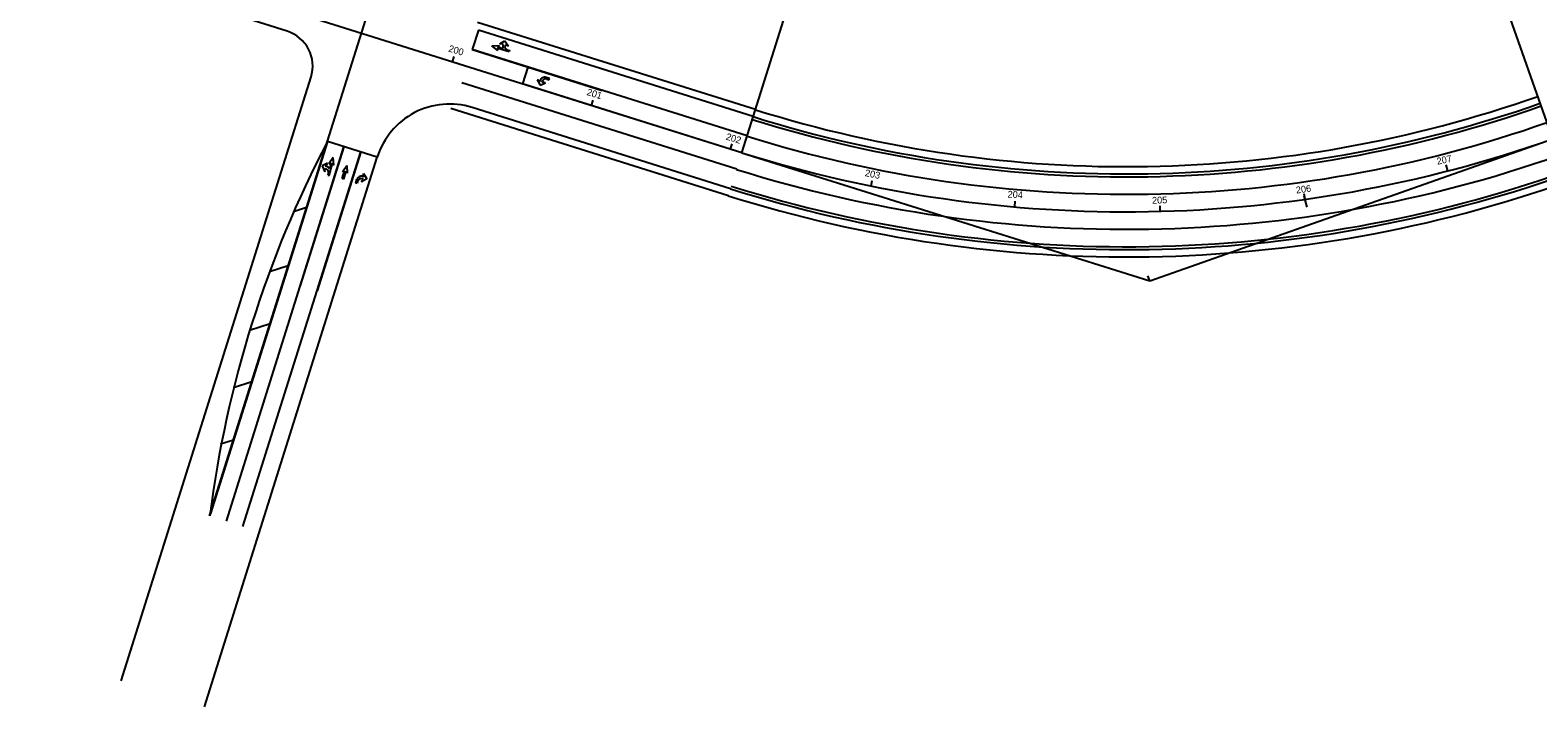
# Model space of a CAD drawing. Extents: x 10803 to 14007, y 6159 to 7440.
# Drawn here: x 10803 to 11838, y 6159 to 6624 of the extents above; entities that cross this region are included whole.
import ezdxf

# ---------------------------------------------------------------- set-up
doc = ezdxf.new("R2010")
doc.units = 0
for name, color, linetype in [('Default', 7, 'Continuous'), ('GE_X_Alignment', 7, 'Continuous'), ('PM_P_Transverse_Line', 7, 'Continuous'), ('PM_X_Cells', 7, 'Continuous'), ('PM_X_Channelizing_Line', 7, 'Continuous'), ('PM_X_CL_Double_Solid', 7, 'Continuous'), ('PM_X_Lane_Line', 7, 'Continuous'), ('PM_X_Stop_Line', 7, 'Continuous'), ('PV_X_Curb', 7, 'Continuous'), ('PV_X_Walk', 7, 'Continuous'), ('SC_Scratch1', 7, 'Continuous')]:
    doc.layers.add(name, color=color, linetype=linetype)

msp = doc.modelspace()

# ---------------------------------------------------------------- linework, layer by layer
at = {"layer": 'Default'}
for p, q in [((11092.8, 6602.1), (11094, 6605.7)), ((11188.2, 6572.1), (11189.4, 6575.7)), ((11283.7, 6542.1), (11284.8, 6545.7)), ((11776.5, 6527.1), (11775.4, 6531.2)), ((11380.3, 6516.7), (11381, 6520.4)), ((11479.1, 6502.4), (11479.4, 6506.2)), ((11678.5, 6507.6), (11677.9, 6511.4)), ((11679.9, 6502.1), (11677.9, 6509.8)), ((11578.9, 6499.4), (11578.8, 6503.1)), ((11571.7, 6451.6), (11570.5, 6454.9))]:
    msp.add_line(p, q, dxfattribs=at)
at = {"layer": 'GE_X_Alignment'}
for p, q in [((10925.9, 6290.1), (11285.2, 7433.1)), ((11291.6, 6539.6), (10806.8, 6692))]:
    msp.add_line(p, q, dxfattribs=at)
msp.add_arc((11555.8, 7380.5), 881.5, 252.5526, 289.4022, dxfattribs=at)
at = {"layer": 'PM_P_Transverse_Line'}
for p, q in [((10992.5, 6501.9), (10983.6, 6499)), ((10979.9, 6461.9), (10967, 6457.7)), ((10967.4, 6422), (10953.4, 6417.5)), ((10954.8, 6382.1), (10942.4, 6378.1)), ((10942.3, 6342.2), (10933.4, 6339.3))]:
    msp.add_line(p, q, dxfattribs=at)
at = {"layer": 'PM_X_Cells'}
for p, q in [((11119.7, 6613), (11125, 6613.2)), ((11124, 6609.9), (11119.7, 6613)), ((11120.2, 6614.6), (11120.2, 6614.6)), ((11131.7, 6608.8), (11123.4, 6611.3)), ((11123.4, 6611.3), (11124, 6609.9)), ((11125, 6613.2), (11123.7, 6612.3)), ((11125.2, 6614.3), (11128.6, 6616.4)), ((11127.6, 6614.2), (11125.2, 6614.3)), ((11127.4, 6613.6), (11127.6, 6614.2)), ((11128.6, 6616.4), (11131.2, 6612.8)), ((11129.1, 6613.8), (11128.9, 6613.1)), ((11131.2, 6612.8), (11129.1, 6613.8)), ((11130.4, 6610.2), (11132, 6609.7)), ((11132, 6609.7), (11131.7, 6608.8)), ((11132.4, 6610.8), (11132.4, 6610.8)), ((11150.9, 6589.7), (11150.9, 6589.7)), ((11152.9, 6588.4), (11150.9, 6589.7)), ((11150.9, 6589.7), (11153, 6586)), ((11153.1, 6589.1), (11152.9, 6588.4)), ((11153, 6586), (11156.6, 6587.6)), ((11154.4, 6588), (11154.6, 6588.6)), ((11156.6, 6587.6), (11154.4, 6588)), ((11159.5, 6590.6), (11157.2, 6591.3)), ((11157.5, 6590.2), (11159.2, 6589.7)), ((11159.2, 6589.7), (11159.5, 6590.6)), ((11158.6, 6587.4), (11158.6, 6587.4)), ((11010.8, 6536.3), (11007.8, 6531.9)), ((11009.2, 6536.7), (11009.2, 6536.7)), ((11011.2, 6531.1), (11010.8, 6536.3)), ((11006.8, 6532.3), (11003.3, 6530.5)), ((11003.3, 6530.5), (11005, 6526.5)), ((11005, 6526.5), (11005.2, 6528.7)), ((11005.2, 6528.7), (11005.9, 6528.5)), ((11005.6, 6530.3), (11006.8, 6532.3)), ((11006.2, 6530.1), (11005.6, 6530.3)), ((11007.5, 6525.7), (11007.1, 6524.1)), ((11007.8, 6531.9), (11009.3, 6532.6)), ((11008.1, 6523.9), (11010.3, 6532.3)), ((11010.3, 6532.3), (11011.2, 6531.1)), ((11016.9, 6521.8), (11018.5, 6527.1)), ((11017.1, 6526.5), (11020.2, 6530.7)), ((11018.5, 6527.1), (11017.1, 6526.5)), ((11019.5, 6526.8), (11017.9, 6521.5)), ((11020.4, 6525.5), (11019.5, 6526.8)), ((11020.2, 6530.7), (11020.2, 6530.7)), ((11020.2, 6530.7), (11020.4, 6525.5)), ((11031.7, 6523.1), (11031.7, 6525.4)), ((11031.7, 6525.4), (11031.7, 6525.4)), ((11031.7, 6525.4), (11033.8, 6521.6)), ((11006, 6524.4), (11006, 6524.4)), ((11007.1, 6524.1), (11008.1, 6523.9)), ((11017.9, 6521.5), (11016.9, 6521.8)), ((11017.4, 6521.7), (11017.4, 6521.7)), ((11026.3, 6518.7), (11027, 6521.1)), ((11027.2, 6518.4), (11026.3, 6518.7)), ((11027.8, 6520.2), (11027.2, 6518.4)), ((11029.5, 6517.7), (11029.5, 6517.7)), ((11033.8, 6521.6), (11030.3, 6519.5)), ((11030.3, 6519.5), (11031.3, 6521.5)), ((11031.3, 6521.5), (11030.6, 6521.7)), ((11031.1, 6523.2), (11031.7, 6523.1))]:
    msp.add_line(p, q, dxfattribs=at)
for points in [[(11123.7, 6612.3), (11127.6, 6611.1)], [(11009.3, 6532.6), (11008.3, 6528.6)]]:
    msp.add_lwpolyline(points, dxfattribs=at)
for centre, radius, start, end in [((11130.5, 6612.6), 3.28, 162.0374, 206.9925), ((11131.1, 6612.4), 2.3, 162.9459, 252.9459), ((11156.2, 6588.2), 3.28, 73.5115, 164.42), ((11156.8, 6588), 2.3, 73.5115, 163.5115), ((11005.3, 6526.3), 2.3, 345.4697, 75.4697), ((11005.5, 6526.9), 3.28, 31.4231, 76.3782), ((11030.1, 6520.1), 3.28, 72.4984, 163.4069), ((11030, 6519.5), 2.3, 73.4069, 163.4069)]:
    msp.add_arc(centre, radius, start, end, dxfattribs=at)
at = {"layer": 'PM_X_Channelizing_Line'}
for p, q in [((11106.3, 6610.4), (11195.5, 6582.4)), ((11018.2, 6543.7), (10988.2, 6448.3)), ((11029.7, 6540.1), (10999.7, 6444.7))]:
    msp.add_line(p, q, dxfattribs=at)
at = {"layer": 'PM_X_CL_Double_Solid'}
for p, q in [((11291.6, 6539.6), (11140.8, 6587)), ((11006.8, 6547.3), (10926.5, 6291.8))]:
    msp.add_line(p, q, dxfattribs=at)
for centre, radius, start, end in [((11682.2, 6193.7), 762.3, 152.3655, 172.7396), ((11555.8, 7380.5), 881.5, 252.5526, 289.4022)]:
    msp.add_arc(centre, radius, start, end, dxfattribs=at)
at = {"layer": 'PM_X_Lane_Line'}
for p, q in [((11295.2, 6551.1), (11106.3, 6610.4)), ((11288, 6528.2), (11099.1, 6587.5)), ((10937.4, 6286.5), (11018.2, 6543.7)), ((10948.8, 6282.9), (11029.7, 6540.1))]:
    msp.add_line(p, q, dxfattribs=at)
for radius in [869.5, 893.5]:
    msp.add_arc((11555.8, 7380.5), radius, 252.5526, 289.4022, dxfattribs=at)
at = {"layer": 'PM_X_Stop_Line'}
for p, q in [((11110.5, 6623.8), (11106.3, 6610.4)), ((11144.4, 6598.4), (11140.8, 6587)), ((11041.1, 6536.6), (11006.8, 6547.3))]:
    msp.add_line(p, q, dxfattribs=at)
at = {"layer": 'PV_X_Curb'}
for radius in [857.5, 905.5]:
    msp.add_arc((11555.8, 7380.5), radius, 252.5526, 289.4022, dxfattribs=at)
at = {"layer": 'PV_X_Walk'}
for p, q in [((10979.2, 6623.1), (10802.6, 6678.6)), ((11300.8, 6569.2), (11110, 6629.1)), ((11299.3, 6564.4), (11110.5, 6623.8)), ((10865.2, 6176.9), (10995.6, 6591.7)), ((11282.3, 6510), (11091.5, 6570)), ((11283.8, 6514.8), (11106.3, 6570.6)), ((10922.4, 6158.9), (11041.1, 6536.6))]:
    msp.add_line(p, q, dxfattribs=at)
for centre, radius, start, end in [((10971.7, 6599.2), 25, 342.5526, 72.5526), ((11555.8, 7380.5), 850.5, 252.5526, 289.4022), ((11090.7, 6521), 52, 72.5526, 162.5526), ((11555.8, 7380.5), 855.5, 252.5526, 289.4022), ((11555.8, 7380.5), 912.5, 252.5526, 289.4022), ((11555.8, 7380.5), 907.5, 252.5526, 289.4022)]:
    msp.add_arc(centre, radius, start, end, dxfattribs=at)
at = {"layer": 'SC_Scratch1'}
for p, q in [((11291.6, 6539.6), (11555.8, 7380.5)), ((11848.7, 6549.1), (11555.8, 7380.5)), ((11571.7, 6451.6), (11848.7, 6549.1)), ((11291.6, 6539.6), (11571.7, 6451.6))]:
    msp.add_line(p, q, dxfattribs=at)

# ---------------------------------------------------------------- texts
at = {"layer": 'Default'}
for s, rotation, p in [('200', 343.0656, (11089.6, 6609.2)), ('201', 343.0656, (11184.6, 6579.3)), ('202', 343.0656, (11280.2, 6548.7)), ('207', 11.9738, (11769.4, 6531.3)), ('203', 348.73, (11375.8, 6523.6)), ('206', 7.679, (11672.5, 6511.5)), ('204', 356.7072, (11474, 6508.8)), ('205', 2.0254, (11573.4, 6504.5))]:
    msp.add_text(s, height=4.68, rotation=rotation, dxfattribs=at).set_placement(p)

doc.saveas('drawing.dxf')
